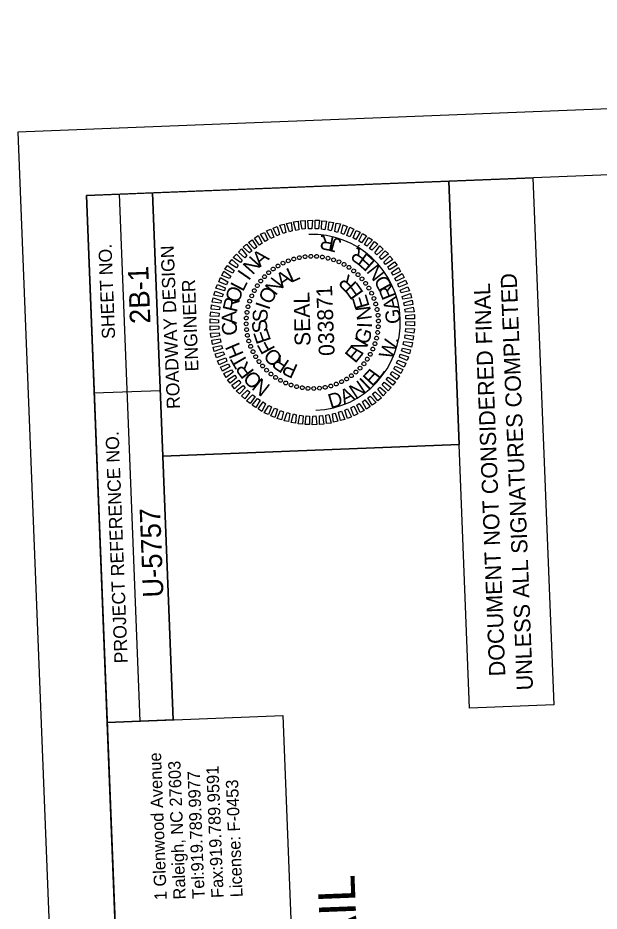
# Model space of a CAD drawing. Extents: x 1627847 to 1629013, y 761524 to 763498.
# Drawn here: x 1627847.2 to 1628067.6, y 762927.1 to 763265.9 of the extents above; entities that cross this region are included whole.
import ezdxf

# ---------------------------------------------------------------- set-up
doc = ezdxf.new("R2010")
doc.units = 0
for name, color, linetype in [('Old_Level_2', 7, 'Continuous'), ('Old_Level_58', 7, 'Continuous'), ('Prop Dimension', 7, 'Continuous'), ('Scratch_Level_0', 7, 'Continuous'), ('Sheet Data Field CELL', 7, 'Continuous'), ('Sheet Plan And Profile CELL', 7, 'Continuous'), ('Sheet Plot Border Outside CELL', 7, 'Continuous'), ('Sheet Professional Seal CELL', 7, 'Continuous'), ('Sheet Profile Grid Minor CELL', 7, 'Continuous'), ('Sheet Sticker Exception Certification CELL', 7, 'Continuous')]:
    doc.layers.add(name, color=color, linetype=linetype)

msp = doc.modelspace()

# ---------------------------------------------------------------- linework, layer by layer
at = {"layer": 'Old_Level_58'}
msp.add_lwpolyline([(1627888.94, 762798.77), (1627881.06, 762998.67), (1627947.7, 763001.3), (1627955.58, 762801.4)], close=True, dxfattribs=at)
at = {"layer": 'Scratch_Level_0'}
msp.add_arc((1627958.87, 763150.38), 33.36, 272.2582, 92.2582, dxfattribs=at)
at = {"layer": 'Sheet Plan And Profile CELL'}
for p, q in [((1627893.6, 762999.16), (1627885.72, 763199.06)), ((1627906.09, 762999.65), (1627898.21, 763199.55)), ((1627876.19, 763123.62), (1627901.17, 763124.61)), ((1627902.2, 763099.63), (1628014.56, 763104.06))]:
    msp.add_line(p, q, dxfattribs=at)
for points in [[(1627873.18, 763198.56), (1627932.28, 761699.73), (1628981.47, 761741.1), (1628922.36, 763239.94)], [(1627902.15, 763099.63), (1627898.21, 763199.55), (1628010.62, 763203.98), (1628014.56, 763104.06)], [(1627881.06, 762998.67), (1627873.18, 763198.56), (1627898.21, 763199.55), (1627906.09, 762999.65)]]:
    msp.add_lwpolyline(points, close=True, dxfattribs=at)
at = {"layer": 'Sheet Plot Border Outside CELL'}
msp.add_lwpolyline([(1629013.34, 761567.22), (1628946.36, 763265.9), (1627847.21, 763222.56), (1627914.2, 761523.88)], close=True, dxfattribs=at)
at = {"layer": 'Sheet Professional Seal CELL'}
for p, q in [((1627949.74, 763173.79), (1627949.74, 763173.79)), ((1627951.81, 763174.47), (1627951.81, 763174.47)), ((1627953.99, 763174.96), (1627953.99, 763174.96)), ((1627956.13, 763175.34), (1627956.13, 763175.34)), ((1627958.33, 763175.48), (1627958.33, 763175.48)), ((1627960.53, 763175.41), (1627960.53, 763175.41)), ((1627962.69, 763175.15), (1627962.69, 763175.15)), ((1627964.81, 763174.78), (1627964.81, 763174.78)), ((1627966.94, 763174.17), (1627966.94, 763174.17)), ((1627968.97, 763173.35), (1627968.97, 763173.35)), ((1627944.01, 763170.61), (1627944.01, 763170.61)), ((1627945.86, 763171.83), (1627945.86, 763171.83)), ((1627947.77, 763172.91), (1627947.77, 763172.91)), ((1627970.96, 763172.42), (1627970.96, 763172.42)), ((1627972.81, 763171.24), (1627972.81, 763171.24)), ((1627974.61, 763169.96), (1627974.61, 763169.96)), ((1627940.72, 763167.73), (1627940.72, 763167.73)), ((1627942.31, 763169.29), (1627942.31, 763169.29)), ((1627976.22, 763168.53), (1627976.22, 763168.53)), ((1627977.78, 763166.94), (1627977.78, 763166.94)), ((1627938, 763164.32), (1627938, 763164.32)), ((1627939.28, 763166.12), (1627939.28, 763166.12)), ((1627979.1, 763165.24), (1627979.1, 763165.24)), ((1627980.32, 763163.38), (1627980.32, 763163.38)), ((1627935.9, 763160.48), (1627935.9, 763160.48)), ((1627936.82, 763162.47), (1627936.82, 763162.47)), ((1627981.4, 763161.48), (1627981.4, 763161.48)), ((1627934.46, 763156.32), (1627934.46, 763156.32)), ((1627935.08, 763158.45), (1627935.08, 763158.45)), ((1627982.28, 763159.51), (1627982.28, 763159.51)), ((1627982.96, 763157.43), (1627982.96, 763157.43)), ((1627934.1, 763154.21), (1627934.1, 763154.21)), ((1627983.44, 763155.25), (1627983.44, 763155.25)), ((1627983.83, 763153.12), (1627983.83, 763153.12)), ((1627933.77, 763149.84), (1627933.77, 763149.84)), ((1627933.83, 763152.04), (1627933.83, 763152.04)), ((1627958.87, 763150.38), (1627958.87, 763150.38)), ((1627983.97, 763150.92), (1627983.97, 763150.92)), ((1627933.91, 763147.64), (1627933.91, 763147.64)), ((1627983.64, 763146.55), (1627983.64, 763146.55)), ((1627983.9, 763148.71), (1627983.9, 763148.71)), ((1627934.29, 763145.51), (1627934.29, 763145.51)), ((1627934.78, 763143.32), (1627934.78, 763143.32)), ((1627983.27, 763144.44), (1627983.27, 763144.44)), ((1627935.46, 763141.25), (1627935.46, 763141.25)), ((1627936.34, 763139.28), (1627936.34, 763139.28)), ((1627981.83, 763140.28), (1627981.83, 763140.28)), ((1627982.65, 763142.31), (1627982.65, 763142.31)), ((1627937.41, 763137.37), (1627937.41, 763137.37)), ((1627979.73, 763136.44), (1627979.73, 763136.44)), ((1627980.91, 763138.29), (1627980.91, 763138.29)), ((1627938.64, 763135.52), (1627938.64, 763135.52)), ((1627939.95, 763133.82), (1627939.95, 763133.82)), ((1627977.01, 763133.03), (1627977.01, 763133.03)), ((1627978.45, 763134.64), (1627978.45, 763134.64)), ((1627941.52, 763132.23), (1627941.52, 763132.23)), ((1627943.13, 763130.79), (1627943.13, 763130.79)), ((1627944.93, 763129.51), (1627944.93, 763129.51)), ((1627973.73, 763130.15), (1627973.73, 763130.15)), ((1627975.43, 763131.47), (1627975.43, 763131.47)), ((1627946.78, 763128.34), (1627946.78, 763128.34)), ((1627948.76, 763127.41), (1627948.76, 763127.41)), ((1627950.8, 763126.59), (1627950.8, 763126.59)), ((1627952.92, 763125.98), (1627952.92, 763125.98)), ((1627963.74, 763125.8), (1627963.74, 763125.8)), ((1627965.92, 763126.29), (1627965.92, 763126.29)), ((1627968, 763126.97), (1627968, 763126.97)), ((1627969.96, 763127.85), (1627969.96, 763127.85)), ((1627971.87, 763128.93), (1627971.87, 763128.93)), ((1627955.04, 763125.61), (1627955.04, 763125.61)), ((1627957.2, 763125.34), (1627957.2, 763125.34)), ((1627959.41, 763125.28), (1627959.41, 763125.28)), ((1627961.6, 763125.42), (1627961.6, 763125.42))]:
    msp.add_line(p, q, dxfattribs=at)
for points in [[(1627945.46, 763183.18), (1627944.05, 763186.17), (1627945.57, 763186.78), (1627946.49, 763183.72)], [(1627947.83, 763184.07), (1627946.56, 763187.22), (1627948.19, 763187.59), (1627948.87, 763184.46)], [(1627950.21, 763184.76), (1627949.13, 763187.87), (1627950.82, 763188.24), (1627951.24, 763185.11)], [(1627952.59, 763185.31), (1627951.76, 763188.53), (1627953.45, 763188.75), (1627953.78, 763185.56)], [(1627954.97, 763185.7), (1627954.44, 763188.94), (1627956.14, 763189.1), (1627956.17, 763185.85)], [(1627957.47, 763185.85), (1627957.19, 763189.09), (1627958.89, 763189.16), (1627958.67, 763185.9)], [(1627959.97, 763185.9), (1627959.94, 763189.15), (1627961.59, 763189.12), (1627961.17, 763185.85)], [(1627962.38, 763185.75), (1627962.55, 763188.95), (1627964.26, 763188.82), (1627963.59, 763185.54)], [(1627964.94, 763185.45), (1627965.22, 763188.56), (1627966.93, 763188.28), (1627966, 763185.09)], [(1627967.36, 763184.89), (1627967.89, 763188.01), (1627969.55, 763187.73), (1627968.43, 763184.53)], [(1627969.79, 763184.24), (1627970.57, 763187.37), (1627972.14, 763186.78), (1627970.86, 763183.73)], [(1627938.9, 763179.72), (1627936.89, 763182.29), (1627938.35, 763183.3), (1627939.87, 763180.45)], [(1627941.04, 763181.1), (1627939.18, 763183.83), (1627940.71, 763184.54), (1627941.97, 763181.74)], [(1627943.15, 763182.18), (1627941.54, 763185.07), (1627943.11, 763185.79), (1627944.23, 763182.73)], [(1627972.03, 763183.32), (1627973.06, 763186.47), (1627974.63, 763185.78), (1627973.15, 763182.87)], [(1627974.37, 763182.42), (1627975.5, 763185.31), (1627977.08, 763184.62), (1627975.34, 763181.85)], [(1627976.56, 763181.3), (1627977.95, 763184.16), (1627979.39, 763183.21), (1627977.49, 763180.54)], [(1627935.01, 763176.76), (1627932.67, 763178.97), (1627933.98, 763180.07), (1627935.98, 763177.5)], [(1627936.9, 763178.34), (1627934.7, 763180.7), (1627936.11, 763181.71), (1627937.82, 763178.97)], [(1627978.62, 763179.88), (1627980.21, 763182.65), (1627981.7, 763181.75), (1627979.59, 763179.27)], [(1627980.58, 763178.46), (1627982.42, 763181.13), (1627983.77, 763180.08), (1627981.5, 763177.79)], [(1627933.28, 763174.94), (1627930.85, 763177), (1627932, 763178.24), (1627934.05, 763175.72)], [(1627982.55, 763176.78), (1627984.49, 763179.41), (1627985.69, 763178.21), (1627983.38, 763176.02)], [(1627984.36, 763175.2), (1627986.47, 763177.49), (1627987.72, 763176.34), (1627985.1, 763174.28)], [(1627930.13, 763171.11), (1627927.31, 763172.85), (1627928.35, 763174.2), (1627930.79, 763172.09)], [(1627931.6, 763173.07), (1627928.92, 763175.02), (1627930.07, 763176.27), (1627932.31, 763174.05)], [(1627985.99, 763173.27), (1627988.3, 763175.51), (1627989.4, 763174.2), (1627986.67, 763172.34)], [(1627987.56, 763171.43), (1627990.04, 763173.38), (1627991.04, 763172.11), (1627988.2, 763170.35)], [(1627927.44, 763167), (1627924.54, 763168.24), (1627925.33, 763169.77), (1627928, 763167.98)], [(1627928.71, 763169.01), (1627925.74, 763170.64), (1627926.74, 763171.98), (1627929.27, 763170.13)], [(1627988.9, 763169.28), (1627991.52, 763171.23), (1627992.38, 763169.71), (1627989.53, 763168.35)], [(1627926.38, 763164.66), (1627923.38, 763165.79), (1627924.02, 763167.37), (1627926.89, 763165.78)], [(1627990.18, 763167.18), (1627992.91, 763168.89), (1627993.67, 763167.36), (1627990.67, 763166.09)], [(1627991.32, 763165.02), (1627994.16, 763166.43), (1627994.82, 763164.96), (1627991.66, 763163.78)], [(1627925.52, 763162.37), (1627922.33, 763163.4), (1627922.87, 763164.82), (1627925.82, 763163.54)], [(1627992.21, 763162.6), (1627995.16, 763163.87), (1627995.67, 763162.34), (1627992.6, 763161.57)], [(1627924.15, 763157.67), (1627920.89, 763158.04), (1627921.22, 763159.75), (1627924.36, 763158.73)], [(1627924.71, 763160.09), (1627921.58, 763160.72), (1627922.02, 763162.29), (1627925.02, 763161.15)], [(1627992.96, 763160.23), (1627996.06, 763161.4), (1627996.48, 763159.72), (1627993.25, 763159.19)], [(1627923.7, 763155.1), (1627920.49, 763155.42), (1627920.67, 763157.08), (1627923.81, 763156.3)], [(1627993.6, 763157.85), (1627996.77, 763158.78), (1627996.98, 763157.14), (1627993.8, 763156.66)], [(1627923.4, 763152.68), (1627920.14, 763152.76), (1627920.38, 763154.42), (1627923.55, 763153.89)], [(1627993.99, 763155.47), (1627997.17, 763156.14), (1627997.44, 763154.45), (1627994.19, 763154.27)], [(1627994.34, 763152.98), (1627997.58, 763153.36), (1627997.59, 763151.71), (1627994.34, 763151.78)], [(1627923.35, 763150.18), (1627920.1, 763150.05), (1627920.08, 763151.7), (1627923.35, 763151.38)], [(1627994.39, 763150.58), (1627997.63, 763150.71), (1627997.65, 763149.06), (1627994.38, 763149.38)], [(1627923.39, 763147.78), (1627920.15, 763147.4), (1627920.14, 763149.05), (1627923.39, 763148.98)], [(1627923.74, 763145.29), (1627920.56, 763144.62), (1627920.3, 763146.31), (1627923.54, 763146.48)], [(1627994.34, 763148.08), (1627997.59, 763148), (1627997.36, 763146.34), (1627994.18, 763146.87)], [(1627924.13, 763142.91), (1627920.97, 763141.98), (1627920.75, 763143.62), (1627923.94, 763144.1)], [(1627993.58, 763143.09), (1627996.85, 763142.72), (1627996.52, 763141.01), (1627993.37, 763142.03)], [(1627994.03, 763145.66), (1627997.25, 763145.34), (1627997.06, 763143.68), (1627993.93, 763144.46)], [(1627924.78, 763140.53), (1627921.67, 763139.36), (1627921.26, 763141.04), (1627924.49, 763141.57)], [(1627993.03, 763140.67), (1627996.15, 763140.04), (1627995.71, 763138.47), (1627992.72, 763139.6)], [(1627925.52, 763138.16), (1627922.57, 763136.89), (1627922.06, 763138.42), (1627925.13, 763139.19)], [(1627926.42, 763135.74), (1627923.57, 763134.33), (1627922.91, 763135.8), (1627926.07, 763136.98)], [(1627991.35, 763136.1), (1627994.35, 763134.97), (1627993.71, 763133.39), (1627990.85, 763134.98)], [(1627992.22, 763138.38), (1627995.41, 763137.36), (1627994.86, 763135.94), (1627991.91, 763137.22)], [(1627927.55, 763133.58), (1627924.82, 763131.87), (1627924.06, 763133.39), (1627927.06, 763134.66)], [(1627990.3, 763133.75), (1627993.2, 763132.52), (1627992.41, 763130.99), (1627989.73, 763132.78)], [(1627928.84, 763131.48), (1627926.21, 763129.53), (1627925.35, 763131.04), (1627928.2, 763132.41)], [(1627930.17, 763129.33), (1627927.7, 763127.38), (1627926.7, 763128.65), (1627929.53, 763130.41)], [(1627987.61, 763129.65), (1627990.43, 763127.91), (1627989.38, 763126.56), (1627986.94, 763128.67)], [(1627989.02, 763131.75), (1627991.99, 763130.12), (1627990.99, 763128.78), (1627988.47, 763130.63)], [(1627931.75, 763127.49), (1627929.43, 763125.25), (1627928.33, 763126.56), (1627931.06, 763128.42)], [(1627933.38, 763125.56), (1627931.26, 763123.27), (1627930.02, 763124.42), (1627932.64, 763126.48)], [(1627984.45, 763125.82), (1627986.89, 763123.76), (1627985.74, 763122.52), (1627983.68, 763125.04)], [(1627986.13, 763127.69), (1627988.81, 763125.74), (1627987.66, 763124.49), (1627985.42, 763126.71)], [(1627935.19, 763123.98), (1627933.24, 763121.35), (1627932.04, 763122.55), (1627934.36, 763124.74)], [(1627937.16, 763122.3), (1627935.31, 763119.63), (1627933.97, 763120.68), (1627936.23, 763122.97)], [(1627980.84, 763122.42), (1627983.03, 763120.06), (1627981.62, 763119.05), (1627979.91, 763121.79)], [(1627982.72, 763124), (1627985.06, 763121.79), (1627983.76, 763120.69), (1627981.75, 763123.26)], [(1627939.11, 763120.88), (1627937.52, 763118.11), (1627936.04, 763119.01), (1627938.14, 763121.49)], [(1627941.17, 763119.46), (1627939.78, 763116.6), (1627938.34, 763117.55), (1627940.24, 763120.22)], [(1627976.69, 763119.66), (1627978.55, 763116.93), (1627977.03, 763116.22), (1627975.77, 763119.02)], [(1627978.84, 763121.04), (1627980.84, 763118.47), (1627979.38, 763117.46), (1627977.87, 763120.3)], [(1627943.37, 763118.34), (1627942.23, 763115.45), (1627940.65, 763116.14), (1627942.39, 763118.91)], [(1627945.7, 763117.44), (1627944.68, 763114.29), (1627943.1, 763114.98), (1627944.59, 763117.89)], [(1627947.94, 763116.52), (1627947.17, 763113.39), (1627945.59, 763113.98), (1627946.87, 763117.03)], [(1627950.37, 763115.87), (1627949.84, 763112.74), (1627948.18, 763113.03), (1627949.31, 763116.23)], [(1627952.79, 763115.31), (1627952.52, 763112.2), (1627950.8, 763112.48), (1627951.73, 763115.67)], [(1627967.53, 763115.99), (1627968.6, 763112.88), (1627966.92, 763112.52), (1627966.49, 763115.65)], [(1627969.9, 763116.69), (1627971.18, 763113.54), (1627969.54, 763113.17), (1627968.87, 763116.3)], [(1627972.27, 763117.58), (1627973.69, 763114.59), (1627972.16, 763113.98), (1627971.24, 763117.04)], [(1627974.58, 763118.57), (1627976.2, 763115.69), (1627974.62, 763114.97), (1627973.5, 763118.03)], [(1627955.36, 763115.01), (1627955.18, 763111.8), (1627953.48, 763111.94), (1627954.15, 763115.22)], [(1627957.77, 763114.86), (1627957.79, 763111.61), (1627956.14, 763111.64), (1627956.56, 763114.91)], [(1627960.27, 763114.91), (1627960.54, 763111.67), (1627958.85, 763111.6), (1627959.07, 763114.86)], [(1627962.76, 763115.06), (1627963.29, 763111.82), (1627961.59, 763111.66), (1627961.57, 763114.91)], [(1627965.15, 763115.45), (1627965.98, 763112.23), (1627964.28, 763112.01), (1627963.96, 763115.2)]]:
    msp.add_lwpolyline(points, close=True, dxfattribs=at)
for centre, major_axis in [((1627947.77, 763172.87), (-0.319, 0.646)), ((1627949.77, 763173.75), (-0.261, 0.671)), ((1627951.85, 763174.46), (-0.202, 0.691)), ((1627953.97, 763174.98), (-0.141, 0.706)), ((1627956.13, 763175.31), (-0.078, 0.716)), ((1627958.32, 763175.45), (-0.016, 0.72)), ((1627960.5, 763175.41), (0.047, 0.718)), ((1627962.68, 763175.17), (0.109, 0.712)), ((1627964.82, 763174.74), (0.171, 0.699)), ((1627966.93, 763174.13), (0.231, 0.682)), ((1627968.96, 763173.34), (0.29, 0.659)), ((1627970.93, 763172.37), (0.346, 0.631)), ((1627942.33, 763169.23), (-0.475, 0.541)), ((1627944.03, 763170.6), (-0.426, 0.581)), ((1627945.85, 763171.82), (-0.374, 0.615)), ((1627972.8, 763171.23), (0.4, 0.599)), ((1627974.56, 763169.94), (0.451, 0.562)), ((1627939.31, 763166.07), (-0.562, 0.451)), ((1627940.75, 763167.72), (-0.52, 0.498)), ((1627976.21, 763168.5), (0.498, 0.52)), ((1627977.72, 763166.92), (0.541, 0.475)), ((1627936.88, 763162.44), (-0.631, 0.346)), ((1627938.01, 763164.31), (-0.599, 0.4)), ((1627979.09, 763165.21), (0.581, 0.426)), ((1627980.31, 763163.39), (0.615, 0.374)), ((1627935.91, 763160.48), (-0.659, 0.29)), ((1627981.36, 763161.48), (0.646, 0.319)), ((1627982.24, 763159.47), (0.671, 0.261)), ((1627934.5, 763156.34), (-0.699, 0.171)), ((1627935.12, 763158.44), (-0.682, 0.231)), ((1627982.94, 763157.4), (0.691, 0.202)), ((1627934.08, 763154.19), (-0.712, 0.109)), ((1627983.46, 763155.28), (0.706, 0.141)), ((1627983.8, 763153.11), (0.716, 0.078)), ((1627933.79, 763149.83), (-0.72, -0.016)), ((1627933.84, 763152.02), (-0.718, 0.047)), ((1627983.89, 763148.74), (0.718, -0.047)), ((1627983.94, 763150.93), (0.72, 0.016)), ((1627933.94, 763147.65), (-0.716, -0.078)), ((1627934.27, 763145.48), (-0.706, -0.141)), ((1627983.66, 763146.57), (0.712, -0.109)), ((1627934.79, 763143.36), (-0.691, -0.202)), ((1627982.62, 763142.32), (0.682, -0.231)), ((1627983.23, 763144.42), (0.699, -0.171)), ((1627935.49, 763141.29), (-0.671, -0.261)), ((1627936.38, 763139.28), (-0.646, -0.319)), ((1627981.82, 763140.28), (0.659, -0.29)), ((1627937.43, 763137.37), (-0.615, -0.374)), ((1627938.64, 763135.55), (-0.581, -0.426)), ((1627979.72, 763136.45), (0.599, -0.4)), ((1627980.86, 763138.32), (0.631, -0.346)), ((1627940.01, 763133.84), (-0.541, -0.475)), ((1627941.53, 763132.26), (-0.498, -0.52)), ((1627976.99, 763133.04), (0.52, -0.498)), ((1627978.43, 763134.68), (0.562, -0.451)), ((1627943.17, 763130.82), (-0.451, -0.562)), ((1627944.94, 763129.52), (-0.4, -0.599)), ((1627946.81, 763128.39), (-0.346, -0.631)), ((1627971.88, 763128.94), (0.374, -0.615)), ((1627973.7, 763130.16), (0.426, -0.581)), ((1627975.41, 763131.53), (0.475, -0.541)), ((1627948.77, 763127.42), (-0.29, -0.659)), ((1627950.81, 763126.63), (-0.231, -0.682)), ((1627952.91, 763126.02), (-0.171, -0.699)), ((1627955.06, 763125.59), (-0.109, -0.712)), ((1627957.23, 763125.35), (-0.047, -0.718)), ((1627959.42, 763125.31), (0.016, -0.72)), ((1627961.6, 763125.45), (0.078, -0.716)), ((1627963.76, 763125.78), (0.141, -0.706)), ((1627965.89, 763126.3), (0.202, -0.691)), ((1627967.96, 763127.01), (0.261, -0.671)), ((1627969.96, 763127.89), (0.319, -0.646))]:
    msp.add_ellipse(centre, major_axis=major_axis, ratio=0.999708, dxfattribs=at)
at = {"layer": 'Sheet Sticker Exception Certification CELL'}
for p, q in [((1628018.49, 763004.09), (1628010.61, 763203.98)), ((1628010.62, 763203.98), (1628042.58, 763205.24)), ((1628042.56, 763205.24), (1628050.44, 763005.35)), ((1628050.44, 763005.35), (1628018.49, 763004.09))]:
    msp.add_line(p, q, dxfattribs=at)

# ---------------------------------------------------------------- texts
at = {"layer": 'Old_Level_2'}
for s, p in [('1 Glenwood Avenue', (1627903.7, 762931.31)), ('Raleigh, NC 27603', (1627910.89, 762931.59)), ('Fax:919.789.9591', (1627925.27, 762932.16)), ('Tel:919.789.9977 ', (1627918.08, 762931.87)), ('License: F-0453', (1627932.46, 762932.44))]:
    msp.add_text(s, height=4.6576, rotation=92.2582, dxfattribs=at).set_placement(p)
at = {"layer": 'Prop Dimension'}
msp.add_text('INTERSECTION DETAIL', height=14, rotation=92.2582, dxfattribs=at).set_placement((1627983.14, 762731.14))
at = {"layer": 'Sheet Data Field CELL'}
for s, p in [('2B-1', (1627897.51, 763149.99)), ('U-5757   ', (1627902.46, 763046.17))]:
    msp.add_text(s, height=7.75, rotation=92.2582, dxfattribs=at).set_placement(p)
at = {"layer": 'Sheet Plan And Profile CELL'}
for s, height, p in [('SHEET NO.', 5, (1627884.13, 763144.25)), ('ROADWAY DESIGN', 5.0001, (1627908.75, 763117.66)), ('ENGINEER', 5, (1627915.74, 763131.9)), ('PROJECT REFERENCE NO.', 5.0001, (1627888.88, 763021.19))]:
    msp.add_text(s, height=height, rotation=92.2582, dxfattribs=at).set_placement(p)
at = {"layer": 'Sheet Professional Seal CELL'}
for s, height, rotation, p in [('A', 5.64, 40.8753, (1627939.08, 763171.22)), ('N', 5.64, 48.0771, (1627936.25, 763168.15)), ('I', 5.64, 55.2783, (1627934.79, 763165.94)), ('L', 5.64, 24.659, (1627950.82, 763165.32)), ('N', 5.64, 52.7348, (1627944.97, 763160.29)), ('A', 5.64, 34.0185, (1627947.45, 763163.24)), ('R', 5.64, 134.7396, (1627976.05, 763165.17)), ('O', 5.64, 69.6794, (1627930.87, 763157.33)), ('L', 5.64, 62.4791, (1627932.55, 763161.8)), ('O', 5.64, 62.0917, (1627943.1, 763156.86)), ('E', 5.64, 125.3823, (1627978.54, 763161.71)), ('R', 5.64, 76.8793, (1627930.25, 763153.95)), ('SEAL', 5.998, 91.2582, (1627958.22, 763141.5)), ('E', 5.64, 106.67, (1627980.69, 763156.49)), ('I', 5.64, 71.4478, (1627942.48, 763154.84)), ('N', 5.64, 97.3146, (1627981.49, 763151.57)), ('A', 5.64, 91.2785, (1627930.22, 763149.75)), ('S', 5.64, 90.1586, (1627941.95, 763150.51)), ('C', 5.64, 98.4781, (1627930.67, 763145.82)), ('S', 5.64, 99.5138, (1627942.14, 763146.92)), ('I', 5.64, 87.9594, (1627981.47, 763148.22)), ('E', 5.64, 108.8693, (1627943.33, 763143.51)), ('G', 5.64, 69.2484, (1627979.83, 763141.6)), ('H', 5.64, 112.8777, (1627932.97, 763138.3)), ('F', 5.64, 118.2252, (1627944.95, 763140.37)), ('N', 5.64, 59.8921, (1627977.73, 763137.71)), ('O', 5.64, 136.9394, (1627948.03, 763137.19)), ('E', 5.64, 50.5351, (1627975.15, 763134.61)), ('T', 5.64, 120.078, (1627934.75, 763135.12)), ('R', 5.64, 127.2787, (1627937.08, 763131.81)), ('R', 5.64, 146.2978, (1627950.55, 763135.54)), ('P', 5.64, 155.6571, (1627953.81, 763134.07)), ('O', 5.64, 134.4799, (1627940.32, 763128.48)), ('N', 5.64, 141.6817, (1627943.3, 763126.3))]:
    msp.add_text(s, height=height, rotation=rotation, dxfattribs=at).set_placement(p)
at = {"layer": 'Sheet Profile Grid Minor CELL'}
for s, height, rotation, p in [('R', 5.5, 169.6122, (1627967.5, 763182.72)), ('.', 5.5, 176.5387, (1627963.54, 763183.52)), ('J', 5.5, 164.7437, (1627970.21, 763181.87)), ('R', 5.5, 144.637, (1627980.35, 763176.05)), (',', 5.5, 151.5634, (1627977.1, 763178.45)), ('E', 5.5, 138.054, (1627983.15, 763173.41)), ('N', 5.5, 128.1223, (1627986.76, 763168.88)), ('D', 5.5, 118.9777, (1627989.34, 763164.21)), ('033871', 5.998, 92.2582, (1627967.38, 763137.81)), ('R', 5.5, 112.0512, (1627990.79, 763160.44)), ('A', 5.5, 103.8654, (1627991.9, 763155.79)), ('G', 5.5, 93.9337, (1627992.33, 763150.01)), ('W', 5.5, 69.1473, (1627989.1, 763136.01)), ('.', 5.5, 80.7534, (1627991.37, 763142.39)), ('E', 5.5, 47.309, (1627981.58, 763125.8)), ('L', 5.5, 53.892, (1627984.25, 763128.57)), ('I', 5.5, 43.7885, (1627980.03, 763124.45)), ('N', 5.5, 33.8568, (1627975.24, 763121.19)), ('D', 5.5, 16.5264, (1627965.81, 763117.64)), ('A', 5.5, 25.671, (1627970.92, 763119.16))]:
    msp.add_text(s, height=height, rotation=rotation, dxfattribs=at).set_placement(p)
at = {"layer": 'Sheet Sticker Exception Certification CELL'}
for s, p in [('UNLESS ALL SIGNATURES COMPLETED', (1628042.58, 763010.94)), ('DOCUMENT NOT CONSIDERED FINAL', (1628032.1, 763016.26))]:
    msp.add_text(s, height=6.124, rotation=92.2582, dxfattribs=at).set_placement(p)

doc.saveas('drawing.dxf')
